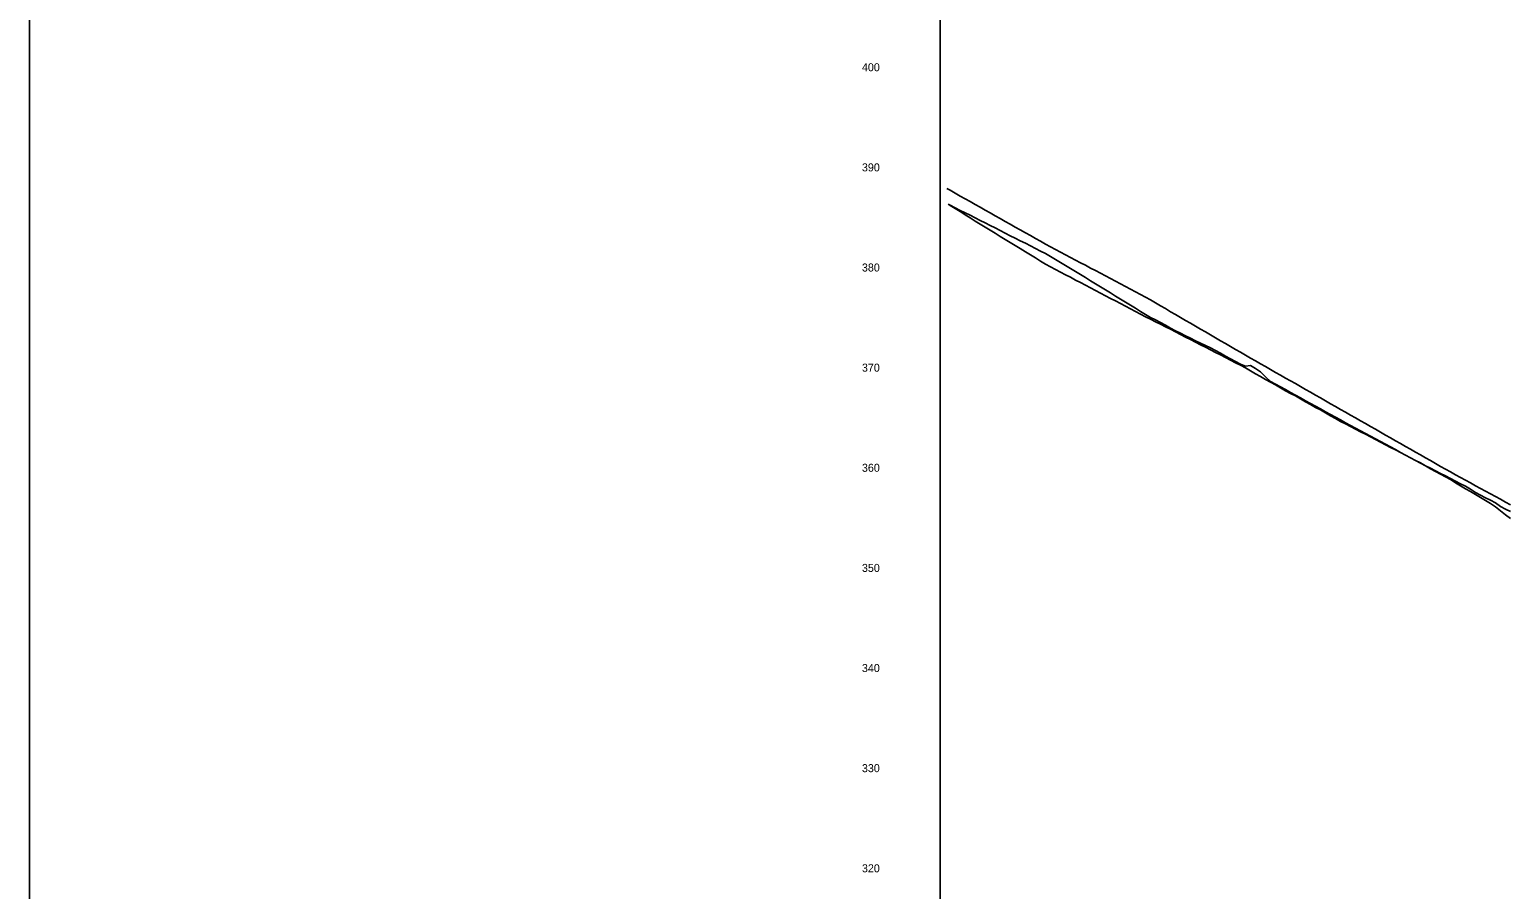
# Model space of a CAD drawing. Extents: x 2005261 to 2010661, y 1001568 to 1006764.
# Drawn here: x 2005261 to 2006738, y 1004253 to 1005112 of the extents above; entities that cross this region are included whole.
import ezdxf

# ---------------------------------------------------------------- set-up
doc = ezdxf.new("R2010")
doc.units = 0
for name, color, linetype in [('RD_DDB_ElevTX', 7, 'Continuous'), ('RD_DDB_Profile_EX', 7, 'Continuous'), ('RD_GPK_Profile_Cell', 7, 'Continuous'), ('RD_Sketch2', 7, 'Continuous'), ('RD_Sketch3', 7, 'Continuous'), ('RD_Sketch4', 7, 'Continuous')]:
    doc.layers.add(name, color=color, linetype=linetype)

msp = doc.modelspace()

# ---------------------------------------------------------------- linework, layer by layer
at = {"layer": 'RD_DDB_Profile_EX'}
for points in [[(2006178.4, 1004953.3), (2006181.7, 1004951.5), (2006186.7, 1004948.7), (2006191.7, 1004945.8), (2006196.7, 1004943), (2006201.7, 1004940.2), (2006206.7, 1004937.4), (2006211.7, 1004934.5), (2006216.7, 1004931.7), (2006221.7, 1004928.9), (2006226.7, 1004926.1), (2006231.7, 1004923.2), (2006236.7, 1004920.4), (2006241.7, 1004917.6), (2006246.7, 1004914.8), (2006251.7, 1004911.9), (2006256.7, 1004909.1), (2006261.7, 1004906.3), (2006266.7, 1004903.5), (2006271.7, 1004900.6), (2006276.7, 1004897.8), (2006281.7, 1004895.1), (2006286.7, 1004892.5), (2006291.7, 1004889.8), (2006296.7, 1004887.2), (2006301.7, 1004884.5), (2006306.7, 1004881.9), (2006311.7, 1004879.2), (2006316.7, 1004876.6), (2006321.7, 1004873.9), (2006326.7, 1004871.3), (2006331.7, 1004868.6), (2006336.7, 1004866), (2006341.7, 1004863.3), (2006346.7, 1004860.7), (2006351.7, 1004858), (2006356.7, 1004855.4), (2006361.7, 1004852.7), (2006366.7, 1004850.1), (2006371.7, 1004847.4), (2006376.7, 1004844.8), (2006381.7, 1004842), (2006386.7, 1004839.1), (2006391.7, 1004836.2), (2006396.7, 1004833.3), (2006401.7, 1004830.3), (2006406.7, 1004827.4), (2006411.7, 1004824.5), (2006416.7, 1004821.6), (2006421.7, 1004818.7), (2006426.7, 1004815.8), (2006431.7, 1004812.9), (2006436.7, 1004810), (2006441.7, 1004807.1), (2006446.7, 1004804.2), (2006451.7, 1004801.3), (2006456.7, 1004798.4), (2006461.7, 1004795.5), (2006466.7, 1004792.6), (2006471.7, 1004789.7), (2006476.7, 1004786.8), (2006481.7, 1004783.9), (2006486.7, 1004781.1), (2006491.7, 1004778.3), (2006496.7, 1004775.4), (2006501.7, 1004772.6), (2006506.7, 1004769.7), (2006511.7, 1004766.9), (2006516.7, 1004764), (2006521.7, 1004761.2), (2006526.7, 1004758.4), (2006531.7, 1004755.5), (2006536.7, 1004752.7), (2006541.7, 1004749.8), (2006546.7, 1004747), (2006551.7, 1004744.1), (2006556.7, 1004741.3), (2006561.7, 1004738.4), (2006566.7, 1004735.6), (2006571.7, 1004732.7), (2006576.7, 1004729.9), (2006581.7, 1004727), (2006586.7, 1004724.2), (2006591.7, 1004721.3), (2006596.7, 1004718.5), (2006601.7, 1004715.7), (2006606.7, 1004712.8), (2006611.7, 1004710), (2006616.7, 1004707.1), (2006621.7, 1004704.3), (2006626.7, 1004701.4), (2006631.7, 1004698.6), (2006636.7, 1004695.7), (2006641.7, 1004692.9), (2006646.7, 1004690), (2006651.7, 1004687.2), (2006656.7, 1004684.4), (2006661.7, 1004681.5), (2006666.7, 1004678.7), (2006671.7, 1004675.8), (2006676.7, 1004673)], [(2006676.7, 1004673), (2006681.7, 1004670.2), (2006686.7, 1004667.5), (2006691.7, 1004664.7), (2006696.7, 1004662), (2006701.7, 1004659.3), (2006706.7, 1004656.5), (2006711.7, 1004653.8), (2006716.7, 1004651.1), (2006721.7, 1004648.4), (2006726.7, 1004645.6), (2006731.7, 1004642.9), (2006736.7, 1004640.2), (2006741.7, 1004637.5)]]:
    msp.add_lwpolyline(points, dxfattribs=at)
at = {"layer": 'RD_GPK_Profile_Cell'}
msp.add_line((2006171.7, 1004068.4), (2006171.7, 1006568.4), dxfattribs=at)
at = {"layer": 'RD_Sketch2'}
for points in [[(2006179.7, 1004937.7), (2006181.7, 1004936.6), (2006186.7, 1004934), (2006191.7, 1004931.5), (2006196.7, 1004929), (2006201.7, 1004926.6), (2006206.7, 1004924), (2006211.7, 1004921.4), (2006216.7, 1004918.9), (2006221.7, 1004916.4), (2006226.7, 1004913.9), (2006231.7, 1004911.4), (2006236.7, 1004908.8), (2006241.7, 1004906.2), (2006246.7, 1004903.6), (2006251.7, 1004901.2), (2006256.7, 1004898.6), (2006261.7, 1004896), (2006266.7, 1004893.4), (2006271.7, 1004890.8), (2006276.7, 1004888.3), (2006281.7, 1004885.5), (2006286.7, 1004882.5), (2006291.7, 1004879.5), (2006296.7, 1004876.4), (2006301.7, 1004873.3), (2006306.7, 1004870.3), (2006311.7, 1004867.3), (2006316.7, 1004864.3), (2006321.7, 1004861.2), (2006326.7, 1004858.1), (2006331.7, 1004855.1), (2006336.7, 1004852), (2006341.7, 1004849), (2006346.7, 1004845.9), (2006351.7, 1004842.8), (2006356.7, 1004839.8), (2006361.7, 1004836.8), (2006366.7, 1004833.7), (2006371.7, 1004830.6), (2006376.7, 1004827.5), (2006381.7, 1004824.6), (2006386.7, 1004822), (2006391.7, 1004819.5), (2006396.7, 1004816.8), (2006401.7, 1004813.9), (2006406.7, 1004811.1), (2006411.7, 1004808.7), (2006416.7, 1004806.3), (2006421.7, 1004803.8), (2006426.7, 1004801.3), (2006431.7, 1004798.7), (2006436.7, 1004796.4), (2006441.7, 1004794.1), (2006446.7, 1004791.4), (2006451.7, 1004788.7), (2006456.7, 1004786), (2006461.7, 1004783.3), (2006466.7, 1004780.6), (2006471.7, 1004777.9), (2006476.7, 1004775.9), (2006481.7, 1004776.4), (2006486.7, 1004773.6), (2006491.7, 1004770.1), (2006496.7, 1004765.2), (2006501.7, 1004760.7), (2006506.7, 1004758), (2006511.7, 1004755.2), (2006516.7, 1004752.5), (2006521.7, 1004749.7), (2006526.7, 1004746.9), (2006531.7, 1004744.2), (2006536.7, 1004741.4), (2006541.7, 1004738.7), (2006546.7, 1004735.9), (2006551.7, 1004733.2), (2006556.7, 1004730.4), (2006561.7, 1004727.7), (2006566.7, 1004724.9), (2006571.7, 1004722.2), (2006576.7, 1004719.4), (2006581.7, 1004716.7), (2006586.7, 1004714.1), (2006591.7, 1004711.4), (2006596.7, 1004708.7), (2006601.7, 1004706.1), (2006606.7, 1004703.3), (2006611.7, 1004700.6), (2006616.7, 1004698), (2006621.7, 1004695.3), (2006626.7, 1004692.6), (2006631.7, 1004689.8), (2006636.7, 1004687.1), (2006641.7, 1004684.4), (2006646.7, 1004681.7), (2006651.7, 1004679), (2006656.7, 1004676.2), (2006661.7, 1004673.4), (2006666.7, 1004670.7), (2006671.7, 1004668), (2006676.7, 1004665.3)], [(2006676.7, 1004665.3), (2006681.7, 1004662.6), (2006686.7, 1004659.5), (2006691.7, 1004656.5), (2006696.7, 1004653.5), (2006701.7, 1004650.6), (2006706.7, 1004647.6), (2006711.7, 1004644.6), (2006716.7, 1004641.6), (2006721.7, 1004638.6), (2006726.7, 1004635.3), (2006731.7, 1004631.3), (2006736.7, 1004627.5), (2006741.7, 1004623.6)]]:
    msp.add_lwpolyline(points, dxfattribs=at)
at = {"layer": 'RD_Sketch3'}
for points in [[(2006179.7, 1004937.5), (2006181.7, 1004936.3), (2006186.7, 1004933.2), (2006191.7, 1004930.2), (2006196.7, 1004927.1), (2006201.7, 1004924), (2006206.7, 1004920.8), (2006211.7, 1004917.8), (2006216.7, 1004914.8), (2006221.7, 1004911.7), (2006226.7, 1004908.6), (2006231.7, 1004905.5), (2006236.7, 1004902.4), (2006241.7, 1004899.4), (2006246.7, 1004896.4), (2006251.7, 1004893.3), (2006256.7, 1004890), (2006261.7, 1004886.9), (2006266.7, 1004883.9), (2006271.7, 1004880.9), (2006276.7, 1004877.9), (2006281.7, 1004875), (2006286.7, 1004872.4), (2006291.7, 1004869.8), (2006296.7, 1004867.2), (2006301.7, 1004864.6), (2006306.7, 1004861.9), (2006311.7, 1004859.3), (2006316.7, 1004856.7), (2006321.7, 1004854.1), (2006326.7, 1004851.5), (2006331.7, 1004848.8), (2006336.7, 1004846.2), (2006341.7, 1004843.6), (2006346.7, 1004841), (2006351.7, 1004838.4), (2006356.7, 1004835.7), (2006361.7, 1004833.1), (2006366.7, 1004830.5), (2006371.7, 1004827.9), (2006376.7, 1004825.3), (2006381.7, 1004822.8), (2006386.7, 1004820.3), (2006391.7, 1004817.7), (2006396.7, 1004815.2), (2006401.7, 1004812.7), (2006406.7, 1004810), (2006411.7, 1004807.5), (2006416.7, 1004805), (2006421.7, 1004802.4), (2006426.7, 1004799.9), (2006431.7, 1004797.2), (2006436.7, 1004794.7), (2006441.7, 1004792.1), (2006446.7, 1004789.6), (2006451.7, 1004787.1), (2006456.7, 1004784.4), (2006461.7, 1004781.8), (2006466.7, 1004779.3), (2006471.7, 1004776.8), (2006476.7, 1004774.1), (2006481.7, 1004771.2), (2006486.7, 1004768.3), (2006491.7, 1004765.4), (2006496.7, 1004762.5), (2006501.7, 1004760), (2006506.7, 1004757.2), (2006511.7, 1004754.3), (2006516.7, 1004751.4), (2006521.7, 1004748.5), (2006526.7, 1004746.1), (2006531.7, 1004743.2), (2006536.7, 1004740.4), (2006541.7, 1004737.5), (2006546.7, 1004734.6), (2006551.7, 1004732.2), (2006556.7, 1004729.3), (2006561.7, 1004726.4), (2006566.7, 1004723.6), (2006571.7, 1004720.7), (2006576.7, 1004718.3), (2006581.7, 1004715.5), (2006586.7, 1004712.9), (2006591.7, 1004710.4), (2006596.7, 1004707.8), (2006601.7, 1004705.2), (2006606.7, 1004702.6), (2006611.7, 1004700), (2006616.7, 1004697.4), (2006621.7, 1004694.8), (2006626.7, 1004692.2), (2006631.7, 1004689.6), (2006636.7, 1004686.9), (2006641.7, 1004684.4), (2006646.7, 1004681.8), (2006651.7, 1004679.2), (2006656.7, 1004676.5), (2006661.7, 1004673.9), (2006666.7, 1004671.3), (2006671.7, 1004668.7), (2006676.7, 1004666.2)], [(2006676.7, 1004666.2), (2006681.7, 1004663.6), (2006686.7, 1004661), (2006691.7, 1004658.5), (2006696.7, 1004655.9), (2006701.7, 1004653.2), (2006706.7, 1004649.6), (2006711.7, 1004647), (2006716.7, 1004644.5), (2006721.7, 1004642), (2006726.7, 1004639.3), (2006731.7, 1004635.8), (2006736.7, 1004633.2), (2006741.7, 1004630.7)]]:
    msp.add_lwpolyline(points, dxfattribs=at)
at = {"layer": 'RD_Sketch4'}
msp.add_lwpolyline([(2005261.5, 1006764.3), (2010661.5, 1006764.3), (2010661.5, 1003464.3), (2005261.5, 1003464.3)], close=True, dxfattribs=at)

# ---------------------------------------------------------------- texts
at = {"layer": 'RD_DDB_ElevTX'}
for s, p in [('400', (2006093.4, 1005070.4)), ('390', (2006093.4, 1004970.4)), ('380', (2006093.4, 1004870.4)), ('370', (2006093.4, 1004770.4)), ('360', (2006093.4, 1004670.4)), ('350', (2006093.4, 1004570.4)), ('340', (2006093.4, 1004470.4)), ('330', (2006093.4, 1004370.4)), ('320', (2006093.4, 1004270.4))]:
    msp.add_text(s, height=8, dxfattribs=at).set_placement(p)

doc.saveas('drawing.dxf')
